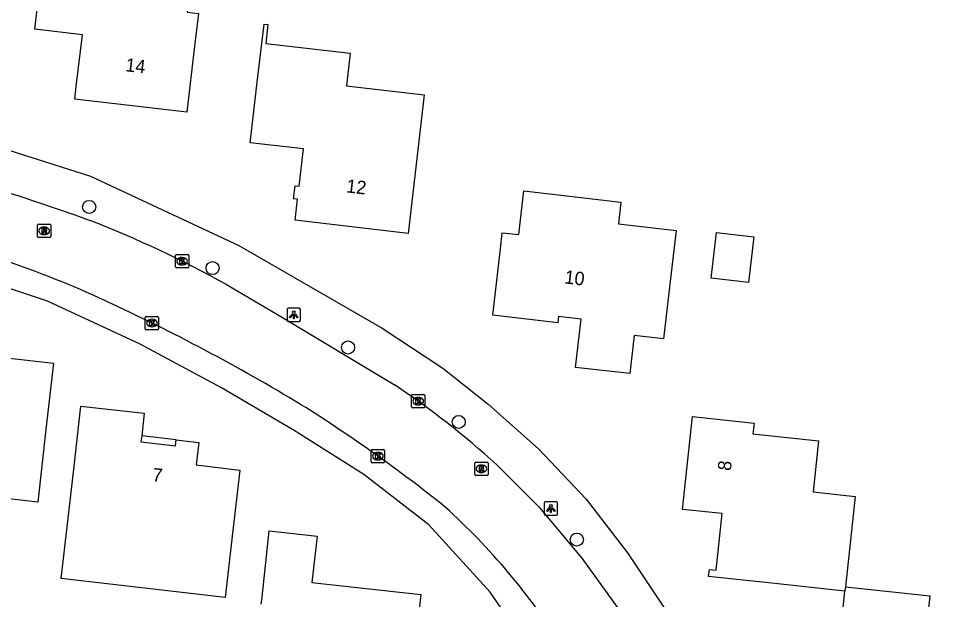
# Model space of a CAD drawing. Extents: x 162398 to 163643, y 386453 to 387397.
# Drawn here: x 163009.8 to 163079.8, y 386866.9 to 386910.4 of the extents above; entities that cross this region are included whole.
import ezdxf

# ---------------------------------------------------------------- set-up
doc = ezdxf.new("R2010")
doc.units = 0
for name, color, linetype in [('IMGEO_Boom', 7, 'Continuous'), ('IMGEO_Kolk', 7, 'Continuous'), ('IMGEO_Lichtpunt', 7, 'Continuous'), ('IMGEO_Pand', 7, 'Continuous'), ('IMGEO_Pand_nummerreeks', 7, 'Continuous'), ('IMGEO_Pand_overbouw', 7, 'Continuous'), ('IMGEO_Parkeervlak_open', 7, 'Continuous'), ('IMGEO_Rijbaan_lokaal_open', 7, 'Continuous'), ('IMGEO_Rioolput', 7, 'Continuous'), ('IMGEO_Voetpad_open', 7, 'Continuous')]:
    doc.layers.add(name, color=color, linetype=linetype)

msp = doc.modelspace()

# ---------------------------------------------------------------- linework, layer by layer
at = {"layer": 'IMGEO_Boom'}
for centre in [(163015.039, 386896.286), (163024.283, 386891.701), (163034.434, 386885.745), (163042.724, 386880.164), (163051.576, 386871.345)]:
    msp.add_circle(centre, 0.489, dxfattribs=at)
at = {"layer": 'IMGEO_Kolk'}
for p, q in [((163021.577, 386892.711), (163022.429, 386892.711)), ((163021.502, 386891.785), (163021.502, 386892.637)), ((163021.99, 386892.491), (163022.015, 386892.491)), ((163022.503, 386892.637), (163022.503, 386891.785)), ((163022.429, 386891.711), (163021.577, 386891.711)), ((163022.013, 386891.931), (163021.988, 386891.931)), ((163019.24, 386887.153), (163019.24, 386888.005)), ((163019.315, 386888.079), (163020.167, 386888.079)), ((163019.728, 386887.859), (163019.753, 386887.859)), ((163020.241, 386888.005), (163020.241, 386887.153)), ((163020.167, 386887.079), (163019.315, 386887.079)), ((163019.751, 386887.299), (163019.726, 386887.299)), ((163039.191, 386881.296), (163039.191, 386882.148)), ((163039.266, 386882.222), (163040.118, 386882.222)), ((163040.192, 386882.148), (163040.192, 386881.296)), ((163039.702, 386881.442), (163039.677, 386881.442)), ((163039.679, 386882.002), (163039.704, 386882.002)), ((163040.118, 386881.222), (163039.266, 386881.222)), ((163036.174, 386877.171), (163036.174, 386878.023)), ((163036.249, 386878.097), (163037.101, 386878.097)), ((163037.175, 386878.023), (163037.175, 386877.171)), ((163036.685, 386877.317), (163036.66, 386877.317)), ((163036.662, 386877.877), (163036.687, 386877.877)), ((163037.101, 386877.097), (163036.249, 386877.097))]:
    msp.add_line(p, q, dxfattribs=at)
for points in [[(163021.577, 386892.711), (163022.429, 386892.711)], [(163021.502, 386891.785), (163021.502, 386892.637)], [(163021.823, 386892.411), (163021.946, 386892.411), (163021.946, 386892.26), (163022.076, 386892.411), (163022.24, 386892.411), (163022.094, 386892.26), (163022.247, 386892.011), (163022.095, 386892.011), (163022.01, 386892.175), (163021.946, 386892.108), (163021.946, 386892.011), (163021.823, 386892.011), (163021.823, 386892.411)], [(163022.503, 386892.637), (163022.503, 386891.785)], [(163022.429, 386891.711), (163021.577, 386891.711)], [(163019.24, 386887.153), (163019.24, 386888.005)], [(163019.315, 386888.079), (163020.167, 386888.079)], [(163019.561, 386887.779), (163019.684, 386887.779), (163019.684, 386887.628), (163019.814, 386887.779), (163019.978, 386887.779), (163019.832, 386887.628), (163019.985, 386887.379), (163019.833, 386887.379), (163019.748, 386887.543), (163019.684, 386887.476), (163019.684, 386887.379), (163019.561, 386887.379), (163019.561, 386887.779)], [(163020.241, 386888.005), (163020.241, 386887.153)], [(163020.167, 386887.079), (163019.315, 386887.079)], [(163039.191, 386881.296), (163039.191, 386882.148)], [(163039.266, 386882.222), (163040.118, 386882.222)], [(163040.192, 386882.148), (163040.192, 386881.296)], [(163039.512, 386881.922), (163039.635, 386881.922), (163039.635, 386881.771), (163039.765, 386881.922), (163039.929, 386881.922), (163039.783, 386881.771), (163039.936, 386881.522), (163039.784, 386881.522), (163039.699, 386881.686), (163039.635, 386881.619), (163039.635, 386881.522), (163039.512, 386881.522), (163039.512, 386881.922)], [(163040.118, 386881.222), (163039.266, 386881.222)], [(163036.174, 386877.171), (163036.174, 386878.023)], [(163036.249, 386878.097), (163037.101, 386878.097)], [(163037.175, 386878.023), (163037.175, 386877.171)], [(163036.495, 386877.797), (163036.618, 386877.797), (163036.618, 386877.646), (163036.748, 386877.797), (163036.912, 386877.797), (163036.766, 386877.646), (163036.919, 386877.397), (163036.767, 386877.397), (163036.682, 386877.561), (163036.618, 386877.494), (163036.618, 386877.397), (163036.495, 386877.397), (163036.495, 386877.797)], [(163037.101, 386877.097), (163036.249, 386877.097)]]:
    msp.add_lwpolyline(points, dxfattribs=at)
for centre, start, end in [((163021.579, 386892.635), 91.55205, 178.44795), ((163021.579, 386892.635), 91.55205, 178.44795), ((163022.427, 386892.635), 1.55205, 88.44795), ((163022.427, 386892.635), 1.55205, 88.44795), ((163021.579, 386891.787), 181.55205, 268.44795), ((163021.579, 386891.787), 181.55205, 268.44795), ((163022.427, 386891.787), 271.55205, 358.44795), ((163022.427, 386891.787), 271.55205, 358.44795), ((163019.317, 386888.003), 91.55205, 178.44795), ((163019.317, 386888.003), 91.55205, 178.44795), ((163020.165, 386888.003), 1.55205, 88.44795), ((163020.165, 386888.003), 1.55205, 88.44795), ((163019.317, 386887.155), 181.55205, 268.44795), ((163019.317, 386887.155), 181.55205, 268.44795), ((163020.165, 386887.155), 271.55205, 358.44795), ((163020.165, 386887.155), 271.55205, 358.44795), ((163039.268, 386882.146), 91.55205, 178.44795), ((163039.268, 386882.146), 91.55205, 178.44795), ((163040.116, 386882.146), 1.55205, 88.44795), ((163040.116, 386882.146), 1.55205, 88.44795), ((163039.268, 386881.298), 181.55205, 268.44795), ((163039.268, 386881.298), 181.55205, 268.44795), ((163040.116, 386881.298), 271.55205, 358.44795), ((163040.116, 386881.298), 271.55205, 358.44795), ((163036.251, 386878.021), 91.55205, 178.44795), ((163036.251, 386878.021), 91.55205, 178.44795), ((163037.099, 386878.021), 1.55205, 88.44795), ((163037.099, 386878.021), 1.55205, 88.44795), ((163036.251, 386877.173), 181.55205, 268.44795), ((163036.251, 386877.173), 181.55205, 268.44795), ((163037.099, 386877.173), 271.55205, 358.44795), ((163037.099, 386877.173), 271.55205, 358.44795)]:
    msp.add_arc(centre, 0.0765, start, end, dxfattribs=at)
for centre, major_axis, ratio, start_param, end_param in [((163021.989, 386892.211), (-0.387, 0.002), 0.722429, 4.712389, 7.853982), ((163022.014, 386892.211), (-0.39, 0.002), 0.717154, 1.570796, 4.712389), ((163019.727, 386887.579), (-0.387, 0.002), 0.722429, 4.712389, 7.853982), ((163019.752, 386887.579), (-0.39, 0.002), 0.717154, 1.570796, 4.712389), ((163039.678, 386881.722), (-0.387, 0.002), 0.722429, 4.712389, 7.853982), ((163039.703, 386881.722), (-0.39, 0.002), 0.717154, 1.570796, 4.712389), ((163036.661, 386877.597), (-0.387, 0.002), 0.722429, 4.712389, 7.853982), ((163036.686, 386877.597), (-0.39, 0.002), 0.717154, 1.570796, 4.712389)]:
    msp.add_ellipse(centre, major_axis=major_axis, ratio=ratio, start_param=start_param, end_param=end_param, dxfattribs=at)
at = {"layer": 'IMGEO_Lichtpunt'}
for p, q in [((163029.865, 386888.593), (163029.865, 386887.786)), ((163029.865, 386888.593), (163029.865, 386887.786)), ((163030.767, 386888.688), (163029.959, 386888.688)), ((163030.767, 386888.688), (163029.959, 386888.688)), ((163030.861, 386887.786), (163030.861, 386888.593)), ((163030.861, 386887.786), (163030.861, 386888.593)), ((163029.959, 386887.692), (163030.767, 386887.692)), ((163029.959, 386887.692), (163030.767, 386887.692)), ((163049.139, 386874.073), (163049.139, 386873.266)), ((163049.139, 386874.073), (163049.139, 386873.266)), ((163050.041, 386874.168), (163049.233, 386874.168)), ((163050.041, 386874.168), (163049.233, 386874.168)), ((163050.135, 386873.266), (163050.135, 386874.073)), ((163050.135, 386873.266), (163050.135, 386874.073)), ((163049.233, 386873.172), (163050.041, 386873.172)), ((163049.233, 386873.172), (163050.041, 386873.172))]:
    msp.add_line(p, q, dxfattribs=at)
for points in [[(163030.239, 386888.257), (163030.278, 386888.229), (163030.09, 386887.967), (163030.052, 386887.994), (163030.239, 386888.257)], [(163030.341, 386888.209), (163030.388, 386888.209), (163030.388, 386887.887), (163030.341, 386887.887), (163030.341, 386888.209)], [(163030.451, 386888.229), (163030.489, 386888.256), (163030.676, 386887.994), (163030.637, 386887.966), (163030.451, 386888.229)], [(163049.513, 386873.737), (163049.552, 386873.709), (163049.364, 386873.447), (163049.326, 386873.474), (163049.513, 386873.737)], [(163049.615, 386873.689), (163049.662, 386873.689), (163049.662, 386873.367), (163049.615, 386873.367), (163049.615, 386873.689)], [(163049.725, 386873.709), (163049.763, 386873.736), (163049.95, 386873.474), (163049.911, 386873.446), (163049.725, 386873.709)]]:
    msp.add_lwpolyline(points, dxfattribs=at)
for centre in [(163030.364, 386888.391), (163049.638, 386873.871)]:
    msp.add_circle(centre, 0.0994, dxfattribs=at)
for centre, start, end in [((163029.959, 386888.593), 90, 180), ((163029.959, 386888.593), 90, 180), ((163030.767, 386888.593), 0, 90), ((163030.767, 386888.593), 0, 90), ((163029.959, 386887.786), 180, 270), ((163029.959, 386887.786), 180, 270), ((163030.767, 386887.786), 270, 0), ((163030.767, 386887.786), 270, 360), ((163049.233, 386874.073), 90, 180), ((163049.233, 386874.073), 90, 180), ((163050.041, 386874.073), 0, 90), ((163050.041, 386874.073), 0, 90), ((163049.233, 386873.266), 180, 270), ((163049.233, 386873.266), 180, 270), ((163050.041, 386873.266), 270, 0), ((163050.041, 386873.266), 270, 360)]:
    msp.add_arc(centre, 0.0946, start, end, dxfattribs=at)
at = {"layer": 'IMGEO_Pand'}
for points in [[(163022.933, 386908.346), (163022.346, 386903.38), (163013.964, 386904.37), (163014.075, 386905.308), (163014.534, 386909.195), (163010.962, 386909.617), (163011.549, 386914.583), (163011.667, 386915.581), (163018.677, 386914.752), (163022.791, 386914.266), (163022.393, 386910.897), (163023.223, 386910.799), (163022.933, 386908.346)], [(163034.314, 386905.364), (163040.143, 386904.69), (163039.515, 386899.269), (163038.94, 386894.302), (163030.476, 386895.282), (163030.658, 386896.855), (163030.356, 386896.89), (163030.469, 386897.865), (163030.772, 386897.83), (163031.096, 386900.632), (163027.107, 386901.093), (163027.681, 386906.054), (163028.138, 386910), (163028.432, 386909.966), (163028.267, 386908.54), (163034.597, 386907.807), (163034.314, 386905.364)], [(163054.872, 386896.644), (163054.686, 386895.025), (163059.011, 386894.526), (163058.645, 386891.352), (163058.072, 386886.384), (163055.872, 386886.638), (163055.543, 386883.784), (163051.483, 386884.252), (163051.9, 386887.869), (163050.208, 386888.065), (163050.155, 386887.601), (163045.28, 386888.163), (163045.852, 386893.131), (163045.993, 386894.351), (163047.224, 386894.209), (163047.601, 386897.482), (163054.872, 386896.644)], [(163062.039, 386894.365), (163064.843, 386894.042), (163064.448, 386890.625), (163061.645, 386890.948), (163062.039, 386894.365)], [(163000, 386883.246), (163003.095, 386882.895), (163003.334, 386885.592), (163003.98, 386885.519), (163012.363, 386884.568), (163011.8, 386879.6), (163011.182, 386874.152), (163002.721, 386875.112), (163002.741, 386875.289), (163000, 386875.6), (162998.856, 386875.73)], [(163014.426, 386881.356), (163019.168, 386880.81), (163018.973, 386879.121), (163018.922, 386878.678), (163021.509, 386878.38), (163021.56, 386878.823), (163023.262, 386878.627), (163023.067, 386876.936), (163026.335, 386876.56), (163025.763, 386871.593), (163025.235, 386867.01), (163016.817, 386867.98), (163012.937, 386868.427), (163013.11, 386869.933), (163013.854, 386876.389), (163014.426, 386881.356)], [(163071.664, 386867.477), (163066.423, 386868.041), (163061.451, 386868.576), (163061.508, 386869.107), (163062.016, 386869.053), (163062.472, 386873.289), (163059.505, 386873.608), (163060.254, 386880.566), (163064.861, 386880.071), (163064.775, 386879.273), (163069.694, 386878.744), (163069.283, 386874.92), (163072.428, 386874.582), (163071.699, 386867.799)], [(163027.93, 386866.492), (163027.989, 386867.028), (163028.537, 386871.997), (163032.111, 386871.603), (163031.728, 386868.133), (163039.897, 386867.232), (163038.931, 386858.483), (163033.962, 386859.031), (163030.538, 386859.409), (163030.8, 386861.783), (163027.451, 386862.153)], [(163071.699, 386867.799), (163078.031, 386867.116), (163077.703, 386864.072), (163071.371, 386864.755), (163071.664, 386867.477)], [(163071.699, 386867.799), (163071.664, 386867.477)]]:
    msp.add_lwpolyline(points, dxfattribs=at)
at = {"layer": 'IMGEO_Pand_overbouw'}
msp.add_lwpolyline([(163021.56, 386878.823), (163018.973, 386879.121), (163018.922, 386878.678), (163021.509, 386878.38)], close=True, dxfattribs=at)
at = {"layer": 'IMGEO_Parkeervlak_open'}
msp.add_lwpolyline([(163058.166, 386847.772), (163048.787, 386862.037), (163045.073, 386867.4), (163040.482, 386872.453), (163035.617, 386876.218), (163030.394, 386879.532), (163024.953, 386882.723), (163018.861, 386886), (163011.909, 386889.211), (163004.674, 386891.621), (163000, 386892.581), (162973.038, 386898.121), (162957.384, 386901.072)], dxfattribs=at)
at = {"layer": 'IMGEO_Rijbaan_lokaal_open'}
for points in [[(162985.263, 386902.621), (163000, 386899.64), (163003.361, 386898.96), (163009.769, 386897.129), (163013.969, 386895.696), (163015.114, 386895.272)], [(163025.325, 386890.459), (163029.16, 386888.213), (163037.976, 386882.913)], [(163045.549, 386876.981), (163048.719, 386873.794), (163051.94, 386869.963), (163054.925, 386865.823), (163055.939, 386864.293), (163058.066, 386861.082), (163070.601, 386842.162), (163072.682, 386839.022), (163084.661, 386820.941), (163086.459, 386818.227), (163088.943, 386814.478), (163089.654, 386813.404), (163097.59, 386801.208), (163098.684, 386799.487)]]:
    msp.add_lwpolyline(points, dxfattribs=at)
for centre, radius, start, end in [((162984.24, 386816.534), 84.575, 60.93638, 68.58951), ((162985.466, 386823.211), 72.857, 64.98181, 78.02347), ((162954.368, 386755), 147.821, 58.81053, 65.24006), ((163001.183, 386828.142), 65.982, 47.74769, 56.10847), ((162969.504, 386783.589), 115.541, 51.33992, 57.88948), ((163007.498, 386836.081), 50.913, 32.33694, 47.82284)]:
    msp.add_arc(centre, radius, start, end, dxfattribs=at)
at = {"layer": 'IMGEO_Rioolput'}
for p, q in [((163011.166, 386894.063), (163011.166, 386894.915)), ((163011.241, 386894.989), (163012.093, 386894.989)), ((163011.654, 386894.769), (163011.679, 386894.769)), ((163012.167, 386894.915), (163012.167, 386894.063)), ((163011.677, 386894.209), (163011.652, 386894.209)), ((163012.093, 386893.989), (163011.241, 386893.989)), ((163043.924, 386876.229), (163043.924, 386877.081)), ((163043.999, 386877.155), (163044.851, 386877.155)), ((163044.412, 386876.935), (163044.437, 386876.935)), ((163044.925, 386877.081), (163044.925, 386876.229)), ((163044.851, 386876.155), (163043.999, 386876.155)), ((163044.435, 386876.375), (163044.41, 386876.375))]:
    msp.add_line(p, q, dxfattribs=at)
for points in [[(163011.166, 386894.063), (163011.166, 386894.915)], [(163011.241, 386894.989), (163012.093, 386894.989)], [(163012.167, 386894.915), (163012.167, 386894.063)], [(163011.755, 386894.687), (163011.503, 386894.689), (163011.503, 386894.289)], [(163011.503, 386894.289), (163011.627, 386894.289), (163011.627, 386894.451), (163011.638, 386894.451)], [(163011.681, 386894.608), (163011.627, 386894.608), (163011.627, 386894.527)], [(163011.627, 386894.527), (163011.679, 386894.527)], [(163011.685, 386894.422), (163011.756, 386894.289), (163011.896, 386894.289), (163011.831, 386894.415)], [(163012.093, 386893.989), (163011.241, 386893.989)], [(163043.924, 386876.229), (163043.924, 386877.081)], [(163043.999, 386877.155), (163044.851, 386877.155)], [(163044.513, 386876.853), (163044.261, 386876.855), (163044.261, 386876.455)], [(163044.261, 386876.455), (163044.385, 386876.455), (163044.385, 386876.617), (163044.396, 386876.617)], [(163044.439, 386876.774), (163044.385, 386876.774), (163044.385, 386876.693)], [(163044.385, 386876.693), (163044.437, 386876.693)], [(163044.443, 386876.588), (163044.514, 386876.455), (163044.654, 386876.455), (163044.589, 386876.581)], [(163044.925, 386877.081), (163044.925, 386876.229)], [(163044.851, 386876.155), (163043.999, 386876.155)]]:
    msp.add_lwpolyline(points, dxfattribs=at)
for centre, radius, start, end in [((163011.243, 386894.913), 0.0765, 91.55205, 178.44795), ((163011.243, 386894.913), 0.0765, 91.55205, 178.44795), ((163012.091, 386894.913), 0.0765, 1.55205, 88.44795), ((163012.091, 386894.913), 0.0765, 1.55205, 88.44795), ((163011.243, 386894.065), 0.0765, 181.55205, 268.44795), ((163011.243, 386894.065), 0.0765, 181.55205, 268.44795), ((163011.637, 386894.398), 0.0533, 26.02933, 88.69889), ((163011.663, 386894.716), 0.19, 274.7715, 282.96867), ((163011.687, 386894.512), 0.0964, 77.00612, 93.18647), ((163011.701, 386894.569), 0.0378, 276.66336, 79.67722), ((163011.754, 386894.577), 0.109, 350.36119, 89.41601), ((163011.752, 386894.577), 0.112, 277.58423, 350.98172), ((163011.736, 386894.362), 0.108, 29.51342, 73.79051), ((163012.091, 386894.065), 0.0765, 271.55205, 358.44795), ((163012.091, 386894.065), 0.0765, 271.55205, 358.44795), ((163044.001, 386877.079), 0.0765, 91.55205, 178.44795), ((163044.001, 386877.079), 0.0765, 91.55205, 178.44795), ((163044.395, 386876.564), 0.0533, 26.02933, 88.69889), ((163044.421, 386876.882), 0.19, 274.7715, 282.96867), ((163044.445, 386876.678), 0.0964, 77.00612, 93.18647), ((163044.459, 386876.735), 0.0378, 276.66336, 79.67722), ((163044.512, 386876.743), 0.109, 350.36119, 89.41601), ((163044.51, 386876.743), 0.112, 277.58423, 350.98172), ((163044.494, 386876.528), 0.108, 29.51342, 73.79051), ((163044.849, 386877.079), 0.0765, 1.55205, 88.44795), ((163044.849, 386877.079), 0.0765, 1.55205, 88.44795), ((163044.001, 386876.231), 0.0765, 181.55205, 268.44795), ((163044.001, 386876.231), 0.0765, 181.55205, 268.44795), ((163044.849, 386876.231), 0.0765, 271.55205, 358.44795), ((163044.849, 386876.231), 0.0765, 271.55205, 358.44795)]:
    msp.add_arc(centre, radius, start, end, dxfattribs=at)
for centre, major_axis, ratio, start_param, end_param in [((163011.653, 386894.489), (-0.387, 0.002), 0.722429, 4.712389, 7.853982), ((163011.678, 386894.489), (-0.39, 0.002), 0.717154, 1.570796, 4.712389), ((163044.411, 386876.655), (-0.387, 0.002), 0.722429, 4.712389, 7.853982), ((163044.436, 386876.655), (-0.39, 0.002), 0.717154, 1.570796, 4.712389)]:
    msp.add_ellipse(centre, major_axis=major_axis, ratio=ratio, start_param=start_param, end_param=end_param, dxfattribs=at)
at = {"layer": 'IMGEO_Voetpad_open'}
msp.add_lwpolyline([(163007.354, 386901.067), (163015.139, 386898.602), (163026.263, 386893.389), (163036.995, 386887.184), (163041.525, 386884.206), (163044.924, 386881.491), (163048.697, 386878.147), (163052.273, 386874.373), (163055.371, 386870.345), (163099.918, 386803.497)], dxfattribs=at)

# ---------------------------------------------------------------- texts
at = {"layer": 'IMGEO_Pand_nummerreeks'}
for s, rotation, p in [('14', 353.26202, (163017.72, 386906.463)), ('12', 353.39544, (163034.265, 386897.381)), ('10', 353.39235, (163050.617, 386890.555)), ('7', 353.42817, (163019.733, 386875.732)), ('8', 83.8581, (163063.112, 386876.466))]:
    msp.add_text(s, height=1, rotation=rotation, dxfattribs=at).set_placement(p)

doc.saveas('drawing.dxf')
